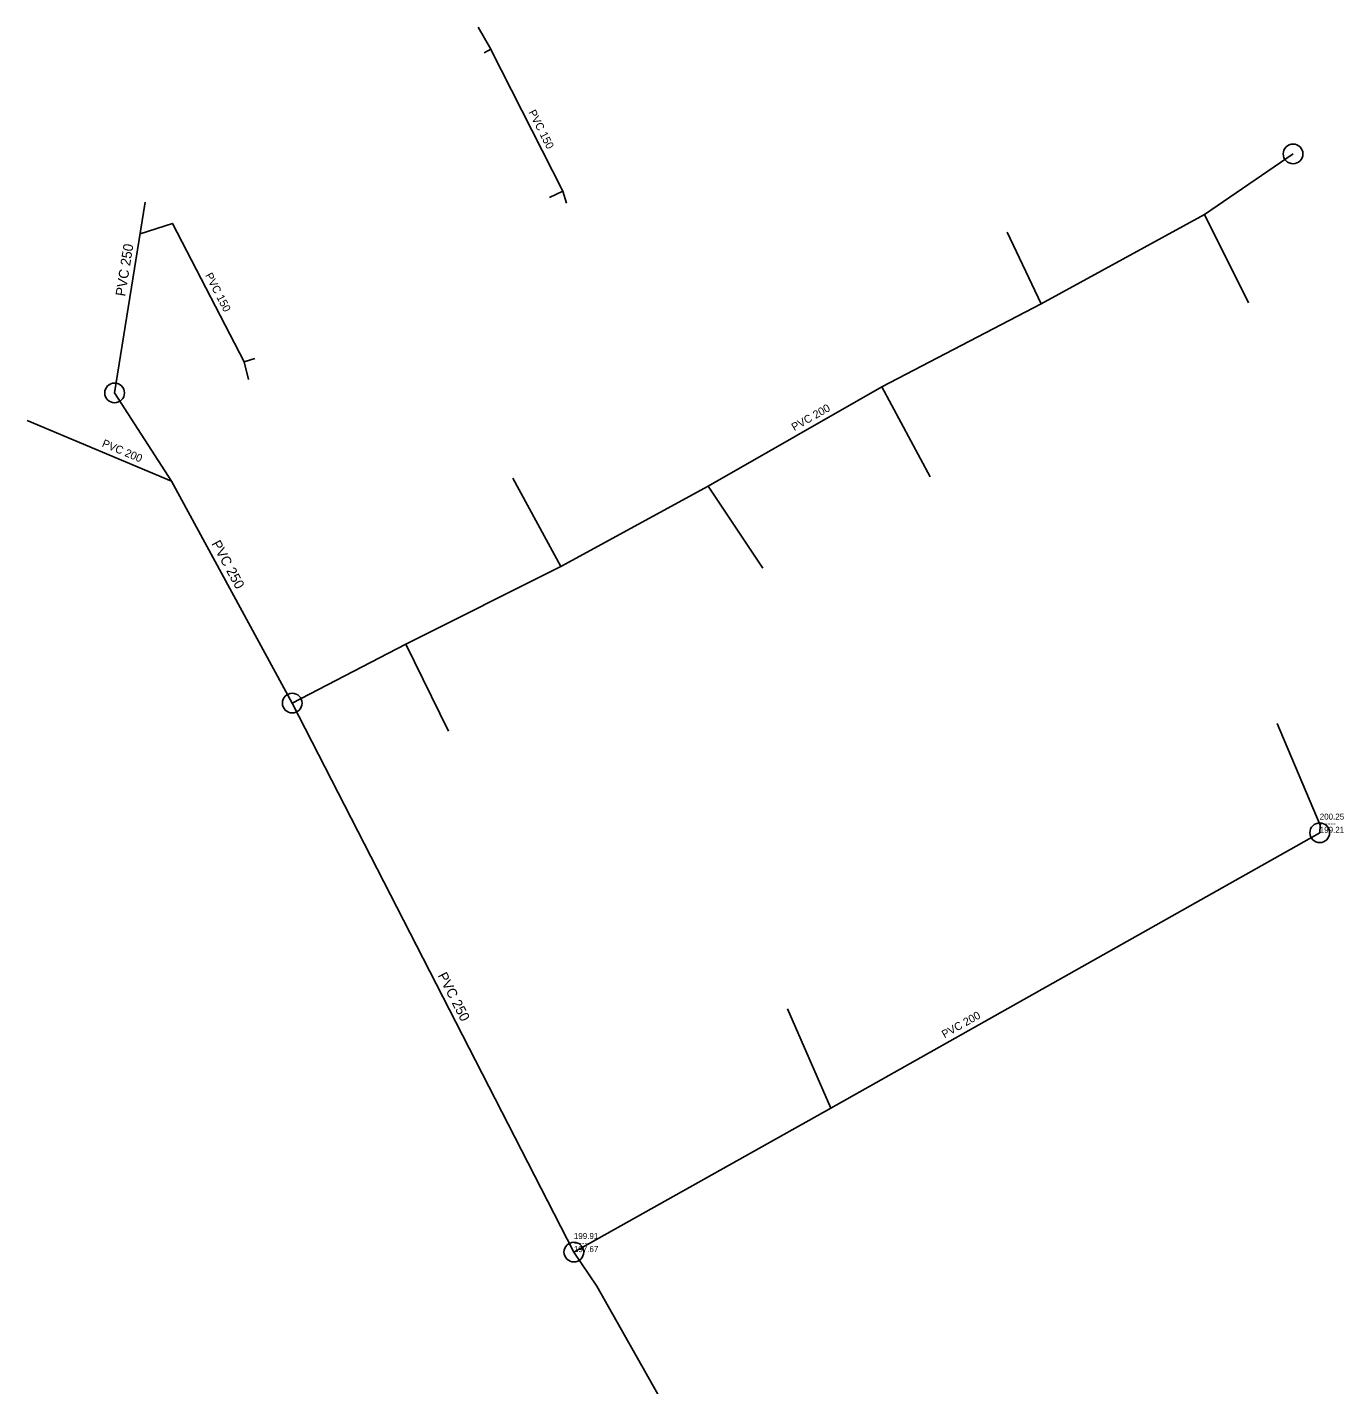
# Model space of a CAD drawing. Extents: x -687957 to -686511, y -1056713 to -1056316.
# Drawn here: x -687458.9 to -687392.1, y -1056434.4 to -1056365.6 of the extents above; entities that cross this region are included whole.
import ezdxf

# ---------------------------------------------------------------- set-up
doc = ezdxf.new("R2010")
doc.units = 0
for name, color, linetype in [('Kanalizační přípojky', 7, 'Continuous'), ('Kanalizační stoka', 7, 'Continuous'), ('Kanalizační šachty', 7, 'Continuous'), ('Popis', 7, 'Continuous')]:
    doc.layers.add(name, color=color, linetype=linetype)

msp = doc.modelspace()

# ---------------------------------------------------------------- linework, layer by layer
at = {"layer": 'Kanalizační přípojky'}
for points in [[(-687431.53, -1056374.5), (-687431.72, -1056373.9), (-687435.37, -1056366.72), (-687435.374, -1056366.712), (-687436.009, -1056365.588)], [(-687435.71, -1056366.89), (-687435.374, -1056366.712), (-687435.37, -1056366.71)], [(-687394.72, -1056372.01), (-687399.2, -1056375.08), (-687407.49, -1056379.61), (-687415.56, -1056383.82), (-687424.36, -1056388.85), (-687431.82, -1056392.92), (-687439.68, -1056396.85), (-687445.43, -1056399.84)], [(-687432.4, -1056374.22), (-687431.72, -1056373.9)], [(-687447.87, -1056382.54), (-687451.5, -1056375.53), (-687453.13, -1056376.06)], [(-687396.97, -1056379.56), (-687399.2, -1056375.08)], [(-687409.2, -1056375.97), (-687407.49, -1056379.61)], [(-687447.32, -1056382.37), (-687447.87, -1056382.54)], [(-687447.64, -1056383.45), (-687447.87, -1056382.54)], [(-687415.56, -1056383.82), (-687413.1, -1056388.37)], [(-687458.86, -1056385.52), (-687451.54, -1056388.59)], [(-687434.26, -1056388.45), (-687431.82, -1056392.92)], [(-687421.59, -1056393), (-687424.36, -1056388.85)], [(-687437.52, -1056401.27), (-687439.68, -1056396.85)], [(-687395.53, -1056400.87), (-687393.35, -1056406.02), (-687393.37, -1056406.41)], [(-687393.37, -1056406.41), (-687418.14, -1056420.36), (-687431.16, -1056427.66)], [(-687420.33, -1056415.33), (-687418.14, -1056420.36)]]:
    msp.add_lwpolyline(points, dxfattribs=at)
at = {"layer": 'Kanalizační stoka'}
for points in [[(-687452.873, -1056374.464), (-687454.43, -1056384.12)], [(-687454.43, -1056384.12), (-687451.54, -1056388.59), (-687445.43, -1056399.84)], [(-687445.43, -1056399.84), (-687431.16, -1056427.66)], [(-687431.16, -1056427.66), (-687429.99, -1056429.39), (-687422.41, -1056442.82), (-687422.18, -1056443.21), (-687417.68, -1056451.7), (-687417.31, -1056452.12), (-687405.32, -1056474.13), (-687404.89, -1056474.51)]]:
    msp.add_lwpolyline(points, dxfattribs=at)
at = {"layer": 'Kanalizační šachty'}
for centre in [(-687394.72, -1056372.01), (-687454.43, -1056384.12), (-687445.43, -1056399.84), (-687393.37, -1056406.41), (-687431.16, -1056427.66)]:
    msp.add_circle(centre, 0.5, dxfattribs=at)

# ---------------------------------------------------------------- texts
at = {"layer": 'Popis'}
for s, height, rotation, p in [('PVC 150', 0.4, 296.94681, (-687433.474, -1056369.898)), ('PVC 250', 0.5, 80.83862, (-687453.898, -1056379.252)), ('PVC 150', 0.4, 297.37655, (-687449.857, -1056378.159)), ('PVC 200', 0.4, 29.75189, (-687419.991, -1056386.065)), ('PVC 200', 0.4, 337.24688, (-687455.103, -1056386.824)), ('PVC 250', 0.5, 298.50688, (-687449.536, -1056391.757)), ('200.25', 0.303, 0, (-687393.37, -1056405.743)), ('------', 0.303, 0, (-687393.37, -1056406.077)), ('199.21', 0.303, 0, (-687393.37, -1056406.41)), ('PVC 250', 0.5, 297.15512, (-687438.073, -1056413.636)), ('PVC 200', 0.4, 29.3874, (-687412.381, -1056416.83)), ('------', 0.303, 360, (-687431.16, -1056427.327)), ('199.91', 0.303, 360, (-687431.16, -1056426.993)), ('197.67', 0.303, 360, (-687431.16, -1056427.66))]:
    msp.add_text(s, height=height, rotation=rotation, dxfattribs=at).set_placement(p)

doc.saveas('drawing.dxf')
